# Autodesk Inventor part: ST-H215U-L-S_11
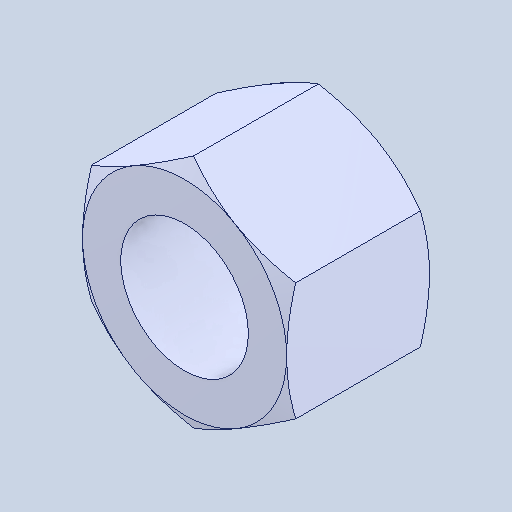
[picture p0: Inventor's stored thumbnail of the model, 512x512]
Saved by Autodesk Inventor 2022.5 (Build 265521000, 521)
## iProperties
Created: 2024-07
Part Number: ST-H215U-L-S_11
Material: 一般
Document SubType Name: Modeling
Designer: ImaoCorp
Density: 1 g/cm^3
Appearance: 既定
Author: ImaoCorp
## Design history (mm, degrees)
feature "ST-H215U-L-S_11"
node "ソリッド1"
